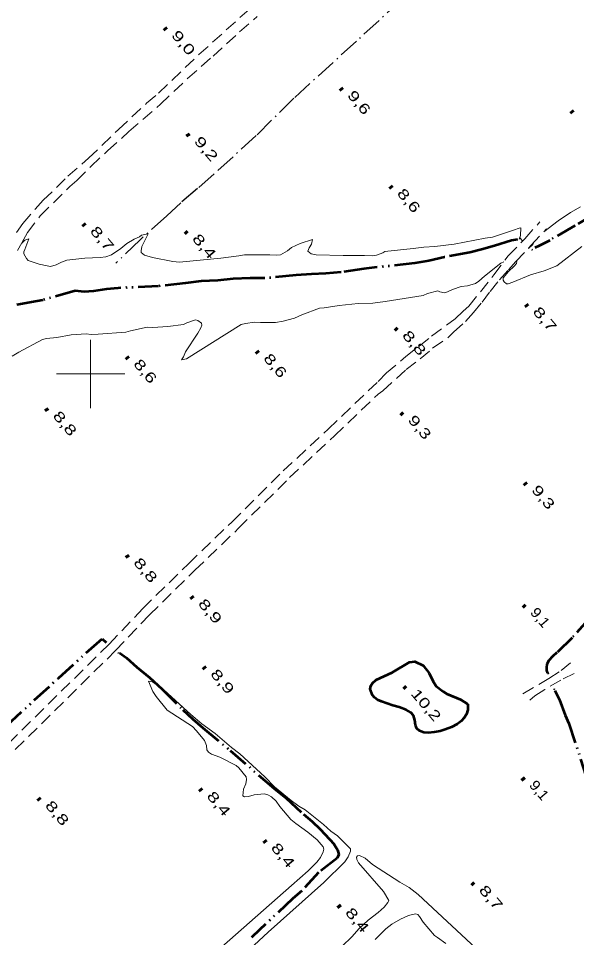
# Model space of a CAD drawing. Extents: x 386081 to 389416, y 5130568 to 5134082.
# Drawn here: x 386578.8 to 386742.5, y 5132434.8 to 5132704.2 of the extents above; entities that cross this region are included whole.
import ezdxf

# ---------------------------------------------------------------- set-up
doc = ezdxf.new("R2010")
doc.units = 0
doc.header["$LTSCALE"] = 1.2
for name, pattern in [('DASH_DOUBLE_DOT', [9.2, 5, -1.2, 0.3, -1.2, 0.3, -1.2]), ('DOT_DASHED', [7.7, 5, -1.2, 0.3, -1.2]), ('MEDIUM_DASHED', [4.5, 3, -1.5])]:
    doc.linetypes.add(name, pattern=pattern)
for name, color, linetype, lineweight in [('1', 7, 'Continuous', 53), ('19', 7, 'Continuous', 13), ('2', 7, 'Continuous', 13), ('26', 7, 'Continuous', 35), ('3', 7, 'Continuous', 140), ('4', 7, 'DASH_DOUBLE_DOT', 53), ('41', 7, 'DOT_DASHED', 25), ('61', 7, 'Continuous', 13)]:
    doc.layers.add(name, color=color, linetype=linetype, lineweight=lineweight)

msp = doc.modelspace()

# ---------------------------------------------------------------- linework, layer by layer
at = {"layer": '1'}
msp.add_lwpolyline([(386710.63, 5132503.15), (386710.57, 5132501.49), (386710.19, 5132500.26), (386709.57, 5132499.15), (386708.64, 5132498.23), (386707.46, 5132497.31), (386705.85, 5132496.46), (386703.99, 5132495.73), (386702.45, 5132495.3), (386700.72, 5132494.94), (386699.11, 5132494.83), (386697.69, 5132494.89), (386696.4, 5132495.33), (386695.66, 5132496.07), (386695.29, 5132497.06), (386695.05, 5132498.54), (386694.63, 5132499.84), (386693.89, 5132500.71), (386692.47, 5132501.51), (386690.44, 5132502.32), (386688.65, 5132502.76), (386685.26, 5132503.95), (386684.15, 5132504.45), (386683.23, 5132505.13), (386682.67, 5132505.81), (386682, 5132507.6), (386682.19, 5132508.53), (386682.69, 5132509.39), (386683.74, 5132510.31), (386688.45, 5132512.5), (386693.46, 5132515.5), (386695.01, 5132515.68), (386697.47, 5132514.56), (386699.25, 5132512.27), (386700.47, 5132509.8), (386701.27, 5132508.5), (386703.36, 5132506.89), (386704.47, 5132506.26), (386708.42, 5132504.52)], close=True, dxfattribs=at)
at = {"layer": '19', "linetype": 'MEDIUM_DASHED'}
for points in [[(386578.24, 5132641.51), (386580.09, 5132644.09), (386583.74, 5132648.33), (386586.1, 5132650.91), (386593.34, 5132657.98), (386599.4, 5132663.25), (386608.14, 5132671.68), (386616.37, 5132679.35), (386619.9, 5132682.36), (386631.76, 5132693.63), (386646.9, 5132707.29)], [(386578.59, 5132636.21), (386579.77, 5132638.48), (386581.51, 5132641.44), (386585.22, 5132646.36), (386593.89, 5132654.96), (386595.94, 5132656.74), (386600.08, 5132660.85), (386604.97, 5132665.46), (386611.22, 5132671.05), (386620.45, 5132679.1), (386628.39, 5132686.6), (386635.89, 5132693.18), (386643.65, 5132700.26), (386648.86, 5132704.81)], [(386547.79, 5132464.05), (386553.95, 5132470.16), (386564.22, 5132479.94), (386575.99, 5132491.8), (386605.39, 5132520.8), (386615.29, 5132531.24), (386628.66, 5132544.38), (386641.47, 5132556.68), (386656.47, 5132571.58), (386669.65, 5132583.84), (386684.27, 5132597.78), (386686.75, 5132600.3), (386692.46, 5132605.09), (386696.3, 5132608.16), (386699.99, 5132611.05), (386706.88, 5132616.21), (386709.24, 5132618.43), (386710.9, 5132619.87), (386718.22, 5132629.04), (386722.43, 5132634.59), (386727.3, 5132639.63), (386731.73, 5132644.61)], [(386577.9, 5132489.88), (386607.32, 5132518.92), (386617.22, 5132529.34), (386630.55, 5132542.44), (386643.36, 5132554.75), (386658.34, 5132569.63), (386671.51, 5132581.88), (386684.29, 5132594.09), (386685.66, 5132595.06), (386692.55, 5132601.26), (386696.58, 5132604.4), (386700.27, 5132607.53), (386705.01, 5132610.85), (386706.44, 5132612.26), (386709.95, 5132615.38), (386712.24, 5132618), (386714.79, 5132621.09), (386717.16, 5132624.21), (386719.93, 5132627.59), (386722.48, 5132630.55), (386724.67, 5132633.01), (386729.21, 5132637.72), (386733.64, 5132642.56)], [(386726.73, 5132506.27), (386734.39, 5132510.72), (386737.94, 5132513.03), (386740.76, 5132515.3)], [(386741.8, 5132512.16), (386737.86, 5132510.26), (386733.13, 5132507.52), (386730.25, 5132505.62), (386728.78, 5132504.35)]]:
    msp.add_lwpolyline(points, dxfattribs=at)
at = {"layer": '2'}
for points in [[(386743.6, 5132649.04), (386740.68, 5132647.34), (386737.11, 5132644.91), (386732.85, 5132641.7)], [(386726.58, 5132638.89), (386725.89, 5132639.98), (386726.01, 5132640.63), (386726.09, 5132642.83), (386725.62, 5132642.74), (386723.98, 5132642.11), (386717.79, 5132640.13), (386715.64, 5132639.8), (386706.61, 5132638.07), (386700.9, 5132637.33), (386697.65, 5132637.22), (386694.57, 5132636.76), (386686.23, 5132635.9), (386685.69, 5132635.53), (386683.85, 5132634.8), (386682.62, 5132634.67), (386680.33, 5132634.76), (386674, 5132634.7), (386666.08, 5132634.93), (386664.62, 5132635.26), (386663.7, 5132635.99), (386664.05, 5132636.99), (386664.75, 5132638.04), (386665.07, 5132639.42), (386661.39, 5132638.25), (386658.9, 5132637.11), (386657.71, 5132636.13), (386655.65, 5132634.96), (386654.57, 5132634.83), (386652.55, 5132634.92), (386645.08, 5132634.93), (386643.47, 5132634.63), (386638.2, 5132633.96), (386626.07, 5132632.79), (386624.1, 5132633.01), (386618.15, 5132634.12), (386615.82, 5132634.87), (386614.81, 5132635.57), (386614.77, 5132636.07), (386615.04, 5132637.38), (386616.84, 5132641.11), (386614.92, 5132640.69), (386614.35, 5132640.16), (386612.75, 5132639.48), (386610.6, 5132638.2), (386608.86, 5132636.78), (386606.1, 5132634.97), (386604.47, 5132634.38), (386602.8, 5132634.18), (386598.32, 5132633.94), (386593.05, 5132633.32), (386591.48, 5132632.8), (386589.87, 5132631.97), (386588.22, 5132631.55), (386587.26, 5132631.66), (386584.94, 5132632.18), (386581.72, 5132633.3), (386581.2, 5132633.84), (386580.38, 5132635.21), (386580.38, 5132635.8), (386580.71, 5132636.49), (386581.9, 5132639.63), (386580.69, 5132639.19), (386579.79, 5132638.38), (386579.7, 5132638.34)], [(386724.71, 5132633.05), (386725, 5132633.01), (386724.87, 5132632.43), (386724.23, 5132631.61), (386722.5, 5132630.05), (386720.99, 5132628.18), (386720.98, 5132627.54), (386721.28, 5132626.99), (386721.93, 5132626.42), (386722.45, 5132626.43), (386723.79, 5132626.9), (386729, 5132629.03), (386732.99, 5132630.21), (386736.7, 5132631.73), (386743.99, 5132637.32)], [(386729.93, 5132638.5), (386729.61, 5132637.96), (386728.52, 5132636.84), (386728.33, 5132636.81)], [(386576.94, 5132605.22), (386578.92, 5132606.42), (386585.84, 5132610.13), (386587.03, 5132610.38), (386590.06, 5132610.69), (386594.3, 5132611.44), (386598.69, 5132611.8), (386600.19, 5132611.58), (386602.22, 5132611.65), (386610.28, 5132612.26), (386611.66, 5132612.68), (386616.53, 5132613.71), (386618.27, 5132613.66), (386622.63, 5132613.88), (386627.25, 5132614.51), (386628.22, 5132615.03), (386630.71, 5132615.91), (386631.43, 5132615.68), (386632.5, 5132614.9), (386632.56, 5132614.26), (386632.3, 5132613.48), (386631.41, 5132611.97), (386627.82, 5132606.47), (386627.26, 5132605.03), (386626.68, 5132604.12), (386628.09, 5132604.42), (386644.18, 5132614.51), (386645.38, 5132614.8), (386648.08, 5132615.16), (386649.77, 5132615.05), (386654.24, 5132615.13), (386656.41, 5132615.5), (386659.76, 5132616.38), (386661.95, 5132617.37), (386667.14, 5132619.26), (386668.46, 5132619.37), (386672.85, 5132620.07), (386678.44, 5132620.65), (386682.72, 5132620.79), (386686.4, 5132621.26), (386697.47, 5132623.04), (386698.74, 5132623.55), (386701.84, 5132624.37), (386702.4, 5132624.11), (386703.8, 5132623.82), (386704.6, 5132624.03), (386706.06, 5132624.76), (386708.64, 5132625.62), (386710.46, 5132625.88), (386712.84, 5132626.54), (386713.83, 5132627.18), (386715.5, 5132628.66), (386720.3, 5132632.5), (386721.12, 5132632.86)], [(386642.52, 5132427.59), (386652.05, 5132436.37), (386668.33, 5132450.94), (386674.57, 5132456.98), (386675.54, 5132458.43), (386676.22, 5132460.07), (386676.16, 5132460.82), (386672.36, 5132464.62), (386670.46, 5132465.96), (386668.29, 5132467.87), (386662.86, 5132472.23), (386661.06, 5132473.26), (386658.82, 5132474.93), (386653.89, 5132478.99), (386651.03, 5132481.86), (386643.75, 5132488.63), (386641.32, 5132490.49), (386636.46, 5132494.55), (386632.59, 5132497.41), (386629.39, 5132500.16), (386620.38, 5132508.36), (386618.78, 5132509.22), (386618.13, 5132509.78), (386616.95, 5132509.98), (386618.24, 5132506.86), (386619.21, 5132505.45), (386622.43, 5132501.4), (386629.82, 5132496.61), (386631.06, 5132495.34), (386633.37, 5132492.51), (386633.98, 5132491.08), (386634.09, 5132489.8), (386634.54, 5132489.09), (386635.43, 5132488.57), (386637.85, 5132487.62), (386642.67, 5132485.26), (386643.44, 5132484.51), (386645.63, 5132481.86), (386645.72, 5132481.13), (386645.51, 5132479.88), (386644.82, 5132478.25), (386644.59, 5132476.28), (386645.15, 5132476.05), (386646.31, 5132476.13), (386647.93, 5132476.57), (386650.84, 5132476.9), (386651.97, 5132476.62), (386653.02, 5132476.01), (386654.37, 5132474.72), (386655.49, 5132473.18), (386658.66, 5132469.43), (386660.13, 5132468.22), (386663.71, 5132465.68), (386666.42, 5132463.38), (386668.18, 5132461.34), (386668.36, 5132460.65), (386668.22, 5132459.87), (386667.43, 5132458.2), (386666.34, 5132456.88), (386663.73, 5132454.3), (386658.93, 5132450.01), (386638.38, 5132432)], [(386714.38, 5132430.25), (386696.08, 5132447.41), (386693.42, 5132449.43), (386690.7, 5132451.04), (386682.6, 5132456.21), (386680.47, 5132458), (386678.8, 5132458.84), (386678.21, 5132458.71), (386677.96, 5132458.3), (386678.05, 5132457.62), (386678.49, 5132456.63), (386685.87, 5132448.23), (386687.42, 5132445.63), (386687.12, 5132445.01), (386686.08, 5132443.73), (386684.29, 5132442.09), (386681.42, 5132439.9), (386678.69, 5132437.4), (386676.61, 5132435.03), (386673.7, 5132432.29)], [(386683.39, 5132434.16), (386686.58, 5132437.37), (386688.36, 5132438.69), (386690.85, 5132440.17), (386693.22, 5132441.23), (386695.27, 5132441.76), (386695.92, 5132441.53), (386696.46, 5132440.96), (386697.54, 5132439.32), (386700.8, 5132435.33), (386701.73, 5132434.8), (386704.13, 5132433.04)]]:
    msp.add_lwpolyline(points, dxfattribs=at)
at = {"layer": '26'}
for p, q in [((386725.68, 5132639.75), (386725.75, 5132639.82)), ((386725.82, 5132639.61), (386725.68, 5132639.75)), ((386725.82, 5132639.61), (386725.89, 5132639.68)), ((386729.52, 5132636.48), (386729.38, 5132636.33)), ((386729.52, 5132636.48), (386729.44, 5132636.55)), ((386729.38, 5132636.33), (386729.31, 5132636.4)), ((386604.29, 5132521.5), (386604.36, 5132521.57)), ((386604.43, 5132521.36), (386604.29, 5132521.5)), ((386604.43, 5132521.36), (386604.5, 5132521.42)), ((386608.05, 5132518.14), (386607.98, 5132518.21)), ((386608.19, 5132518.28), (386608.05, 5132518.14)), ((386608.19, 5132518.28), (386608.12, 5132518.35)), ((386734.05, 5132512.16), (386734.09, 5132512.26)), ((386734.24, 5132512.1), (386734.05, 5132512.16)), ((386734.24, 5132512.1), (386734.28, 5132512.19)), ((386735.85, 5132507.5), (386735.82, 5132507.59)), ((386736.04, 5132507.56), (386735.85, 5132507.5)), ((386736.04, 5132507.56), (386736.01, 5132507.66))]:
    msp.add_line(p, q, dxfattribs=at)
at = {"layer": '3'}
for p, q in [((386621.62, 5132701.45), (386622.13, 5132700.84)), ((386673.22, 5132683.83), (386673.73, 5132683.22)), ((386740.87, 5132677.13), (386741.38, 5132676.52)), ((386628.29, 5132670.36), (386628.8, 5132669.75)), ((386687.8, 5132655.07), (386688.31, 5132654.46)), ((386597.79, 5132644.03), (386598.3, 5132643.42)), ((386627.75, 5132641.77), (386628.26, 5132641.16)), ((386727.61, 5132620.4), (386728.12, 5132619.79)), ((386689.32, 5132613.45), (386689.83, 5132612.84)), ((386610.53, 5132605.05), (386611.04, 5132604.44)), ((386648.65, 5132606.69), (386649.16, 5132606.08)), ((386586.88, 5132589.85), (386587.39, 5132589.24)), ((386690.99, 5132588.63), (386691.5, 5132588.02)), ((386727.24, 5132568.12), (386727.75, 5132567.51)), ((386610.52, 5132546.83), (386611.03, 5132546.22)), ((386629.47, 5132534.79), (386629.98, 5132534.18)), ((386726.86, 5132532.2), (386727.37, 5132531.59)), ((386633.08, 5132514.18), (386633.59, 5132513.57)), ((386691.86, 5132508.39), (386692.37, 5132507.78)), ((386726.57, 5132481.55), (386727.08, 5132480.94)), ((386631.99, 5132478.37), (386632.5, 5132477.76)), ((386584.61, 5132475.62), (386585.12, 5132475.01)), ((386650.83, 5132463.23), (386651.34, 5132462.62)), ((386711.81, 5132450.83), (386712.32, 5132450.22)), ((386672.61, 5132444.24), (386673.12, 5132443.63))]:
    msp.add_line(p, q, dxfattribs=at)
at = {"layer": '4'}
for points in [[(386860.9, 5132683.86), (386859.61, 5132683.55), (386854.96, 5132683.01), (386852.04, 5132682.46), (386845.64, 5132680.81), (386840.43, 5132679.35), (386830.8, 5132676.97), (386828.14, 5132676.17), (386821.41, 5132673.54), (386812.4, 5132669.8), (386807.25, 5132667.78), (386793.53, 5132663.19), (386782.18, 5132660.07), (386777.96, 5132659.1), (386761.52, 5132654.76), (386757.55, 5132652.8), (386742.09, 5132643.52), (386734.61, 5132639.17), (386731.51, 5132637.57), (386730.21, 5132637.02)], [(386725.2, 5132639.45), (386723.41, 5132639.15), (386718.45, 5132637.56), (386714.61, 5132636.46), (386711.14, 5132635.61), (386703.77, 5132634.21), (386699.12, 5132633.18), (386695.03, 5132632.45), (386680.14, 5132630.84), (386673.46, 5132629.88), (386668.94, 5132629.46), (386664.79, 5132629.29), (386660.22, 5132628.94), (386651, 5132628.05), (386646.79, 5132628.06), (386641.78, 5132627.9), (386637.33, 5132627.42), (386632.39, 5132627.19), (386627.81, 5132626.59), (386619.89, 5132625.75), (386608.03, 5132625.18), (386604.69, 5132624.82), (386600.79, 5132624.28), (386598.14, 5132624.11), (386595.42, 5132624.36), (386586.02, 5132621.68), (386584.29, 5132621.32), (386577.98, 5132620.23)], [(386746.58, 5132528.73), (386741.17, 5132522.64), (386736.7, 5132518.34), (386735.39, 5132517.17), (386734.33, 5132516), (386733.77, 5132514.96), (386733.64, 5132513.97), (386733.7, 5132513.04), (386733.95, 5132512.3)], [(386544.47, 5132468.01), (386567.23, 5132489.38), (386590.53, 5132510.83), (386599.51, 5132518.97), (386603.38, 5132522.37), (386604.59, 5132521.3)], [(386608.41, 5132518.29), (386610.5, 5132516.8), (386613.58, 5132514.08), (386617.21, 5132511.04), (386620.96, 5132507.63), (386626.99, 5132501.55), (386629.94, 5132498.82), (386632.9, 5132496.22), (386640.9, 5132489.64), (386653.85, 5132478.45), (386657.29, 5132475.6), (386662.4, 5132470.94), (386664.93, 5132468.77), (386667.27, 5132466.54), (386671.45, 5132462.07), (386672.37, 5132460.52), (386672.74, 5132459.16), (386672.24, 5132458.06), (386666.84, 5132453.83), (386661.93, 5132448.48), (386659.33, 5132446.27), (386649.52, 5132437.07), (386647.17, 5132434.74)], [(386736.15, 5132507.23), (386737.44, 5132504.44), (386739.15, 5132499.99), (386740.25, 5132497.52), (386745.23, 5132482.23), (386747.89, 5132475.71), (386750.58, 5132468.78), (386751.81, 5132465.32), (386754.38, 5132459), (386758.14, 5132448.03), (386760.96, 5132441.84), (386763.17, 5132437.51), (386763.97, 5132436.21), (386764.27, 5132435.4), (386764.39, 5132434.66), (386765.15, 5132432.79)]]:
    msp.add_lwpolyline(points, dxfattribs=at)
at = {"layer": '41'}
msp.add_lwpolyline([(386698.16, 5132716.16), (386677.93, 5132697.58), (386659.62, 5132680.88), (386648.57, 5132669.93), (386636.2, 5132658.63), (386631.37, 5132654.33), (386626.41, 5132650.15), (386622.31, 5132646.34), (386614.53, 5132639.34), (386607.37, 5132632.46)], dxfattribs=at)
at = {"layer": '61'}
for p, q in [((386600, 5132590), (386600, 5132610)), ((386590, 5132600), (386610, 5132600))]:
    msp.add_line(p, q, dxfattribs=at)

# ---------------------------------------------------------------- texts
at = {"layer": '3'}
for s, width, p in [('9,0    ', 1.45, (386623.45, 5132699.23)), ('9,6    ', 1.4, (386675.05, 5132681.61)), ('9,2    ', 1.45, (386630.12, 5132668.14)), ('8,6    ', 1.4, (386689.63, 5132652.85)), ('8,7    ', 1.45, (386599.62, 5132641.81)), ('8,4    ', 1.45, (386629.58, 5132639.55)), ('8,7    ', 1.45, (386729.44, 5132618.18)), ('8,8    ', 1.45, (386691.15, 5132611.23)), ('8,6    ', 1.4, (386612.36, 5132602.83)), ('8,6    ', 1.4, (386650.48, 5132604.47)), ('8,8    ', 1.45, (386588.71, 5132587.63)), ('9,3    ', 1.4, (386692.82, 5132586.41)), ('9,3    ', 1.4, (386729.07, 5132565.9)), ('8,8    ', 1.45, (386612.35, 5132544.61)), ('8,9    ', 1.45, (386631.3, 5132532.57)), ('9,1    ', 1.1, (386728.69, 5132529.98)), ('8,9    ', 1.45, (386634.91, 5132511.96)), ('10,2   ', 1.4, (386693.69, 5132506.17)), ('9,1    ', 1.1, (386728.4, 5132479.33)), ('8,4    ', 1.45, (386633.82, 5132476.15)), ('8,8    ', 1.45, (386586.44, 5132473.4)), ('8,4    ', 1.45, (386652.66, 5132461.01)), ('8,7    ', 1.45, (386713.64, 5132448.61)), ('8,4    ', 1.45, (386674.44, 5132442.02))]:
    msp.add_text(s, height=3, rotation=310.294, dxfattribs=dict(at, width=width)).set_placement(p)

doc.saveas('drawing.dxf')
